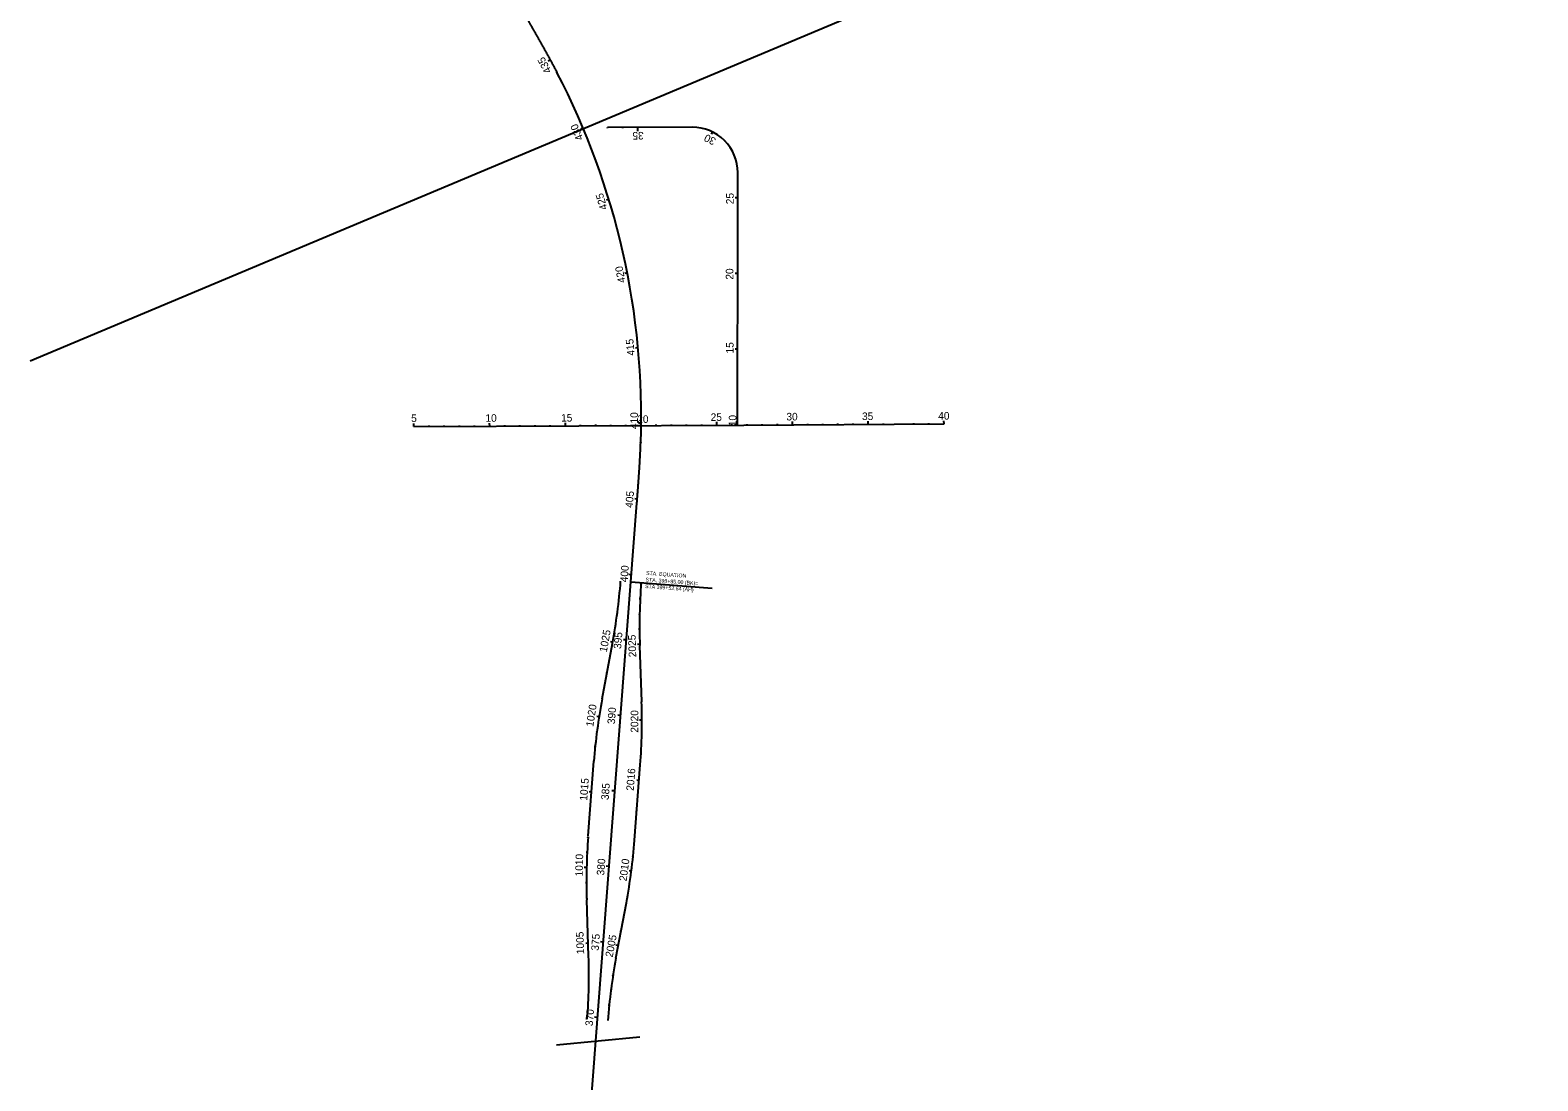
# Model space of a CAD drawing. Extents: x 448091 to 665917, y 1461380 to 1587607.
# Drawn here: x 480103 to 490058, y 1554798 to 1561735 of the extents above; entities that cross this region are included whole.
import ezdxf

# ---------------------------------------------------------------- set-up
doc = ezdxf.new("R2010")
doc.units = 0
for name, color, linetype in [('AsphaltMisc', 7, 'Continuous'), ('Attenuator_ep', 7, 'Continuous'), ('BarrierWall_ep', 7, 'Continuous'), ('TextShtNo', 7, 'Continuous'), ('TextTitle', 7, 'Continuous')]:
    doc.layers.add(name, color=color, linetype=linetype)

msp = doc.modelspace()

# ---------------------------------------------------------------- linework, layer by layer
at = {"layer": 'AsphaltMisc'}
for p, q in [((483913.5, 1561091.9), (483913.5, 1561088.1)), ((484474.5, 1561094.3), (483914.9, 1561091.9)), ((484013.5, 1561092.3), (484013.5, 1561088.6)), ((484113.5, 1561092.7), (484113.6, 1561068.2)), ((484213.5, 1561093.2), (484213.5, 1561089.4)), ((484313.5, 1561093.6), (484313.5, 1561089.9)), ((484413.5, 1561094), (484413.5, 1561090.3)), ((484513.4, 1561092), (484512.9, 1561088.2)), ((484608.7, 1561063.3), (484601, 1561047.6)), ((484689.4, 1561005), (484686.7, 1561002.4)), ((484746.6, 1560923.5), (484743.2, 1560921.9)), ((484774, 1560827.8), (484770.2, 1560827.4)), ((484775.9, 1560459.8), (484775.8, 1560794.3)), ((484775.9, 1560727.9), (484772.1, 1560727.9)), ((484775.9, 1560627.9), (484758.4, 1560627.9)), ((484775.9, 1560527.9), (484772.1, 1560527.9)), ((484775.9, 1560427.9), (484772.1, 1560427.9)), ((484774.9, 1559127.9), (484775.9, 1560459.8)), ((484775.8, 1560327.9), (484772, 1560327.9)), ((484775.7, 1560227.9), (484772, 1560227.9)), ((484775.6, 1560127.9), (484758.1, 1560127.9)), ((484775.6, 1560027.9), (484771.8, 1560027.9)), ((484775.5, 1559927.9), (484771.8, 1559927.9)), ((484775.4, 1559827.9), (484771.7, 1559827.9)), ((484775.4, 1559727.9), (484771.6, 1559727.9)), ((484775.3, 1559627.9), (484757.8, 1559627.9)), ((484775.2, 1559527.9), (484771.5, 1559527.9)), ((484775.1, 1559427.9), (484771.4, 1559427.9)), ((484775.1, 1559327.9), (484771.3, 1559327.9)), ((484775, 1559227.9), (484771.2, 1559227.9)), ((484774.9, 1559127.9), (484753.4, 1559127.9))]:
    msp.add_line(p, q, dxfattribs=at)
msp.add_arc((484475.8, 1560794.3), 300, 0.00667, 90.24889, dxfattribs=at)
at = {"layer": 'Attenuator_ep'}
msp.add_line((484070.1, 1558092.9), (484606.9, 1558052), dxfattribs=at)
msp.add_circle((484070.1, 1558092.9), 1.24, dxfattribs=at)
at = {"layer": 'BarrierWall_ep'}
msp.add_line((480103.3, 1559552.9), (490058.4, 1563731.6), dxfattribs=at)
at = {"layer": 'TextShtNo'}
for p, q in [((482637.5, 1559118.4), (484814.9, 1559128.1)), ((484814.9, 1559128.1), (486137.4, 1559135)), ((484045.9, 1557775.9), (484109.7, 1558612.2)), ((484070.1, 1558092.9), (484109.7, 1558612.2)), ((484070.1, 1558092.9), (484109.7, 1558612.2)), ((483762.6, 1554061.5), (484045.9, 1557775.9)), ((483879.7, 1557320.2), (483948.2, 1557686)), ((484141.1, 1557300.2), (484128.9, 1557672.2)), ((483788.1, 1556415.5), (483825.6, 1556908.1)), ((484094, 1556386.2), (484132.1, 1556884.7)), ((483790.8, 1555622), (483778.6, 1555994)), ((483971.4, 1555608.2), (484039.9, 1555974.1)), ((483579.4, 1555036.9), (484129.2, 1555088.6))]:
    msp.add_line(p, q, dxfattribs=at)
for centre, radius, start, end in [((479226.7, 1559185.3), 4911.1, 357.97112, 27.53647), ((480193.7, 1558388.6), 3819.7, 349.40062, 355.63779), ((487946.6, 1557797.2), 3819.7, 175.63779, 181.87496), ((487634.3, 1556617.6), 3819.7, 169.40062, 175.63779), ((480323.4, 1557175.2), 3819.7, 355.63779, 1.87496), ((487596.2, 1556119), 3819.7, 175.63779, 181.87496), ((480285.4, 1556676.7), 3819.7, 349.40061, 355.63779), ((479973.1, 1555497), 3819.7, 355.63779, 1.87496), ((487726.5, 1554905.5), 3820.2, 169.40061, 175.63779)]:
    msp.add_arc(centre, radius, start, end, dxfattribs=at)
for points in [[(483387, 1561805.2), (483389.7, 1561800.5), (483392.4, 1561795.9), (483395.1, 1561791.2), (483397.8, 1561786.5), (483400.5, 1561781.8), (483403.1, 1561777.1), (483405.8, 1561772.4), (483408.5, 1561767.7), (483411.2, 1561763), (483413.9, 1561758.3), (483416.6, 1561753.7), (483419.3, 1561749), (483422, 1561744.3), (483424.7, 1561739.6), (483427.3, 1561734.9), (483430, 1561730.2), (483432.7, 1561725.5), (483435.4, 1561720.8), (483438.1, 1561716.1), (483440.7, 1561711.4), (483443.4, 1561706.7), (483446.1, 1561702), (483448.8, 1561697.3), (483451.4, 1561692.6), (483454.1, 1561687.9), (483456.8, 1561683.2), (483459.5, 1561678.5), (483462.1, 1561673.8), (483464.8, 1561669.1), (483467.4, 1561664.4), (483470.1, 1561659.7), (483472.8, 1561655), (483475.4, 1561650.3), (483478.1, 1561645.6), (483480.7, 1561640.9), (483483.4, 1561636.2), (483486, 1561631.5), (483488.7, 1561626.7), (483491.3, 1561622), (483493.9, 1561617.3), (483496.6, 1561612.6), (483499.2, 1561607.9), (483501.8, 1561603.1), (483504.5, 1561598.4), (483507.1, 1561593.7), (483509.7, 1561589), (483512.3, 1561584.2), (483514.9, 1561579.5), (483517.5, 1561574.8), (483520.1, 1561570), (483522.7, 1561565.3), (483525.3, 1561560.6), (483527.9, 1561555.8), (483530.5, 1561551.1), (483533.1, 1561546.3), (483535.7, 1561541.6), (483538.3, 1561536.8), (483540.9, 1561532.1), (483543.4, 1561527.3), (483546, 1561522.6), (483548.6, 1561517.8), (483551.1, 1561513), (483553.7, 1561508.3), (483556.2, 1561503.5), (483558.8, 1561498.7), (483561.3, 1561494), (483563.9, 1561489.2), (483566.4, 1561484.4), (483568.9, 1561479.7), (483571.4, 1561474.9), (483573.9, 1561470.1), (483576.5, 1561465.3), (483579, 1561460.5), (483581.5, 1561455.7)], [(484109.7, 1558612.2), (484110.1, 1558617.6), (484110.5, 1558623), (484111, 1558628.4), (484111.4, 1558633.8), (484111.8, 1558639.2), (484112.2, 1558644.6), (484112.6, 1558649.9), (484113, 1558655.3), (484113.4, 1558660.7), (484113.8, 1558666.1), (484114.2, 1558671.5), (484114.6, 1558676.9), (484115, 1558682.3), (484115.4, 1558687.7), (484115.8, 1558693.1), (484116.2, 1558698.5), (484116.7, 1558703.8), (484117, 1558709.2), (484117.4, 1558714.6), (484117.8, 1558720), (484118.2, 1558725.4), (484118.6, 1558730.8), (484119, 1558736.2), (484119.4, 1558741.6), (484119.8, 1558747), (484120.2, 1558752.4), (484120.6, 1558757.8), (484120.9, 1558763.1), (484121.3, 1558768.5), (484121.7, 1558773.9), (484122.1, 1558779.3), (484122.4, 1558784.7), (484122.8, 1558790.1), (484123.2, 1558795.5), (484123.5, 1558800.9), (484123.9, 1558806.3), (484124.3, 1558811.7), (484124.6, 1558817.1), (484125, 1558822.5), (484125.3, 1558827.9), (484125.7, 1558833.3), (484126, 1558838.7), (484126.3, 1558844), (484126.7, 1558849.4), (484127, 1558854.8), (484127.3, 1558860.2), (484127.7, 1558865.6), (484128, 1558871), (484128.3, 1558876.4), (484128.6, 1558881.8), (484128.9, 1558887.2), (484129.2, 1558892.6), (484129.5, 1558898), (484129.8, 1558903.4), (484130.1, 1558908.8), (484130.4, 1558914.2), (484130.7, 1558919.6), (484131, 1558925), (484131.2, 1558930.4), (484131.5, 1558935.8), (484131.8, 1558941.2), (484132, 1558946.6), (484132.3, 1558952), (484132.5, 1558957.4), (484132.8, 1558962.8), (484133, 1558968.2), (484133.3, 1558973.6), (484133.5, 1558979), (484133.7, 1558984.4), (484133.9, 1558989.8), (484134.1, 1558995.2), (484134.3, 1559000.6), (484134.5, 1559006), (484134.7, 1559011.4)]]:
    msp.add_spline(points, degree=3, dxfattribs=at)
at = {"layer": 'TextTitle'}
for p, q in [((483440.5, 1561711.9), (483436.8, 1561709.7)), ((483440.5, 1561711.9), (483437.5, 1561710.2)), ((483489.7, 1561624.8), (483486, 1561622.7)), ((483489.7, 1561624.8), (483486.8, 1561623.2)), ((483538, 1561537.3), (483523.6, 1561529.4)), ((483538.1, 1561537.3), (483534.3, 1561535.2)), ((483585, 1561449), (483581.2, 1561447)), ((483585, 1561449), (483582, 1561447.4)), ((483715.1, 1561178.7), (483711.1, 1561176.9)), ((483715, 1561178.7), (483711.9, 1561177.3)), ((483754.7, 1561086.9), (483739.6, 1561080.5)), ((483754.7, 1561086.9), (483750.7, 1561085.2)), ((483792.5, 1560994.3), (483788.5, 1560992.7)), ((483792.5, 1560994.3), (483789.3, 1560993)), ((483828.4, 1560901), (483824.3, 1560899.4)), ((483828.4, 1560901), (483825.2, 1560899.8)), ((483862.4, 1560806.9), (483858.3, 1560805.5)), ((483862.4, 1560806.9), (483859.1, 1560805.8)), ((483894.4, 1560712.2), (483890.3, 1560710.8)), ((483894.4, 1560712.2), (483891.2, 1560711.1)), ((483924.5, 1560616.8), (483908.8, 1560612.1)), ((483924.5, 1560616.8), (483920.4, 1560615.6)), ((483952.7, 1560520.9), (483948.6, 1560519.7)), ((483952.7, 1560520.9), (483949.4, 1560520)), ((483978.9, 1560424.4), (483974.8, 1560423.3)), ((483978.9, 1560424.4), (483975.6, 1560423.5)), ((484003.2, 1560327.4), (483999, 1560326.4)), ((484003.2, 1560327.4), (483999.9, 1560326.6)), ((484025.4, 1560229.9), (484021.2, 1560229)), ((484025.4, 1560229.9), (484022.1, 1560229.2)), ((484045.7, 1560132), (484029.6, 1560128.8)), ((484045.7, 1560132), (484041.5, 1560131.1)), ((484064, 1560033.6), (484059.7, 1560032.9)), ((484064, 1560033.6), (484060.6, 1560033.1)), ((484080.2, 1559935), (484076, 1559934.3)), ((484080.2, 1559935), (484076.9, 1559934.5)), ((484094.5, 1559836), (484090.2, 1559835.4)), ((484094.5, 1559836), (484091.1, 1559835.6)), ((484106.7, 1559736.8), (484102.5, 1559736.3)), ((484106.7, 1559736.8), (484103.4, 1559736.4)), ((484117, 1559637.3), (484100.6, 1559635.8)), ((484117, 1559637.3), (484112.7, 1559636.9)), ((484125.2, 1559537.6), (484120.9, 1559537.3)), ((484125.2, 1559537.6), (484121.8, 1559537.4)), ((484131.3, 1559437.8), (484127, 1559437.6)), ((484131.3, 1559437.8), (484127.9, 1559437.6)), ((484135.4, 1559337.9), (484131.1, 1559337.8)), ((484135.4, 1559337.9), (484132, 1559337.8)), ((484137.5, 1559237.9), (484133.2, 1559237.9)), ((484137.5, 1559237.9), (484134.1, 1559237.9)), ((482637.5, 1559118.4), (482637.4, 1559139.1)), ((482737.5, 1559118.8), (482737.4, 1559124.6)), ((482837.5, 1559119.3), (482837.4, 1559125)), ((482937.5, 1559119.7), (482937.4, 1559125.5)), ((483037.5, 1559120.1), (483037.4, 1559125.9)), ((483137.5, 1559120.6), (483137.4, 1559141.3)), ((483237.5, 1559121), (483237.4, 1559126.8)), ((483337.5, 1559121.5), (483337.4, 1559127.2)), ((483437.4, 1559121.9), (483437.4, 1559127.7)), ((483537.4, 1559122.4), (483537.4, 1559128.1)), ((483637.4, 1559122.8), (483637.4, 1559143.6)), ((483737.4, 1559123.3), (483737.4, 1559129)), ((483837.4, 1559123.7), (483837.4, 1559131.5)), ((483837.4, 1559123.7), (483837.4, 1559129.5)), ((483937.4, 1559124.2), (483937.4, 1559129.9)), ((484037.4, 1559124.6), (484037.4, 1559130.4)), ((484137.6, 1559137.9), (484121.2, 1559138.1)), ((484137.6, 1559137.9), (484133.3, 1559138)), ((484137.4, 1559125.1), (484137.4, 1559135.8)), ((484237.4, 1559125.5), (484237.4, 1559131.3)), ((484337.4, 1559126), (484337.4, 1559131.7)), ((484437.4, 1559126.4), (484437.4, 1559132.2)), ((484537.4, 1559126.9), (484537.4, 1559132.6)), ((484637.4, 1559127.3), (484637.3, 1559148.1)), ((484737.4, 1559127.7), (484737.4, 1559133.5)), ((484837.4, 1559128.2), (484837.4, 1559134)), ((484937.4, 1559128.7), (484937.4, 1559134.5)), ((485037.4, 1559129.2), (485037.4, 1559135)), ((485137.4, 1559129.8), (485137.3, 1559150.5)), ((485237.4, 1559130.3), (485237.4, 1559136)), ((485337.4, 1559130.8), (485337.4, 1559136.6)), ((485437.4, 1559131.3), (485437.4, 1559137.1)), ((485537.4, 1559131.8), (485537.4, 1559137.6)), ((485637.4, 1559132.4), (485637.3, 1559153.1)), ((485737.4, 1559132.9), (485737.4, 1559138.6)), ((485837.4, 1559133.4), (485837.4, 1559139.2)), ((485937.4, 1559133.9), (485937.4, 1559139.7)), ((486037.4, 1559134.4), (486037.4, 1559140.2)), ((486137.4, 1559135), (486137.3, 1559155.7)), ((484135.6, 1559037.9), (484131.3, 1559038.1)), ((484135.6, 1559037.9), (484132.2, 1559038)), ((484131.6, 1558938), (484127.3, 1558938.2)), ((484131.6, 1558938), (484128.2, 1558938.2)), ((484126, 1558838.2), (484121.7, 1558838.5)), ((484126, 1558838.2), (484122.6, 1558838.4)), ((484119.2, 1558738.4), (484114.9, 1558738.7)), ((484119.2, 1558738.4), (484115.8, 1558738.7)), ((484111.7, 1558638.7), (484095.4, 1558639.9)), ((484111.7, 1558638.7), (484107.5, 1558639)), ((484104.1, 1558539), (484099.9, 1558539.3)), ((484104.1, 1558539), (484100.7, 1558539.2)), ((484096.5, 1558439.3), (484092.2, 1558439.6)), ((484096.5, 1558439.3), (484093.1, 1558439.5)), ((484088.9, 1558339.6), (484084.6, 1558339.9)), ((484088.9, 1558339.6), (484085.5, 1558339.8)), ((484081.3, 1558239.9), (484077, 1558240.2)), ((484081.3, 1558239.9), (484077.9, 1558240.1)), ((484001.7, 1558090.4), (483996, 1558090.9)), ((484073.7, 1558140.1), (484057.4, 1558141.4)), ((484073.7, 1558140.1), (484069.4, 1558140.5)), ((484137.3, 1558080.1), (484131.6, 1558080.5)), ((483992.6, 1557990.9), (483986.9, 1557991.4)), ((484063.6, 1558008.2), (484058.7, 1558008.6)), ((484131.2, 1557980.3), (484125.5, 1557980.5)), ((483980.9, 1557891.5), (483975.2, 1557892.3)), ((484056, 1557908.5), (484051.1, 1557908.8)), ((484127.8, 1557880.3), (484122, 1557880.5)), ((483966.6, 1557792.6), (483960.9, 1557793.5)), ((484048.4, 1557808.8), (484043.5, 1557809.1)), ((484126.9, 1557780.3), (484121.2, 1557780.3)), ((483949.7, 1557694), (483934.2, 1557696.9)), ((484040.8, 1557709), (484020.9, 1557710.6)), ((484128.6, 1557680.4), (484112.9, 1557679.9)), ((483931.3, 1557595.7), (483925.7, 1557596.8)), ((484033.2, 1557609.3), (484028.2, 1557609.7)), ((484131.9, 1557580.4), (484126.2, 1557580.2)), ((483912.9, 1557497.4), (483907.3, 1557498.5)), ((484025.6, 1557509.6), (484020.6, 1557510)), ((484135.2, 1557480.5), (484129.4, 1557480.3)), ((483894.5, 1557399.1), (483888.9, 1557400.2)), ((484018, 1557409.9), (484013, 1557410.3)), ((484138.4, 1557380.5), (484132.7, 1557380.3)), ((483859.6, 1557202.2), (483844, 1557204.6)), ((484002.8, 1557210.5), (483982.9, 1557212)), ((484143.1, 1557180.6), (484127.4, 1557180.6)), ((483845.6, 1557103.2), (483839.9, 1557103.9)), ((483995.2, 1557110.8), (483990.2, 1557111.2)), ((484141.9, 1557080.6), (484136.2, 1557080.7)), ((483834.1, 1557003.9), (483828.4, 1557004.4)), ((483987.6, 1557011.1), (483982.6, 1557011.5)), ((484138.2, 1556980.7), (484132.4, 1556981)), ((483825.3, 1556904.3), (483819.6, 1556904.7)), ((483980, 1556911.4), (483975, 1556911.7)), ((484131.8, 1556880.9), (484126, 1556881.3)), ((483817.7, 1556804.5), (483812, 1556805)), ((483972.4, 1556811.7), (483967.4, 1556812)), ((484124.2, 1556781.2), (484108.5, 1556782.4)), ((483810.1, 1556704.8), (483794.4, 1556706)), ((483964.8, 1556711.9), (483944.8, 1556713.5)), ((484116.5, 1556681.5), (484110.8, 1556681.9)), ((483802.5, 1556605.1), (483796.8, 1556605.6)), ((483957.2, 1556612.2), (483952.2, 1556612.6)), ((484108.9, 1556581.8), (484103.2, 1556582.2)), ((483794.9, 1556505.4), (483789.2, 1556505.9)), ((483949.6, 1556512.5), (483944.6, 1556512.9)), ((484101.3, 1556482), (484095.6, 1556482.5)), ((483787.3, 1556405.7), (483781.6, 1556406.1)), ((483942, 1556412.8), (483937, 1556413.2)), ((484093.7, 1556382.3), (484088, 1556382.8)), ((483781.1, 1556305.9), (483775.4, 1556306.2)), ((483934.3, 1556313.1), (483929.4, 1556313.5)), ((484084.7, 1556282.7), (484079, 1556283.3)), ((483777.5, 1556206), (483761.8, 1556206.3)), ((483926.7, 1556213.4), (483906.8, 1556214.9)), ((484073.1, 1556183.4), (484057.5, 1556185.4)), ((483776.6, 1556106), (483770.8, 1556106)), ((483919.1, 1556113.7), (483914.1, 1556114.1)), ((484058.9, 1556084.4), (484053.2, 1556085.3)), ((483778.2, 1556006), (483772.5, 1556005.8)), ((483911.5, 1556014), (483906.5, 1556014.3)), ((484042.1, 1555985.9), (484036.5, 1555986.9)), ((483781.5, 1555906), (483775.7, 1555905.9)), ((483903.9, 1555914.3), (483898.9, 1555914.6)), ((484023.7, 1555887.6), (484018.1, 1555888.6)), ((483784.7, 1555806.1), (483779, 1555805.9)), ((483896.3, 1555814.5), (483891.3, 1555814.9)), ((484005.3, 1555789.3), (483999.7, 1555790.3)), ((483788, 1555706.2), (483772.3, 1555705.6)), ((483888.7, 1555714.8), (483868.8, 1555716.4)), ((483986.9, 1555691), (483971.5, 1555693.9)), ((483791.2, 1555606.2), (483785.5, 1555606)), ((483881.1, 1555615.1), (483876.1, 1555615.5)), ((483968.6, 1555592.7), (483962.9, 1555593.7)), ((483792.8, 1555506.2), (483787.1, 1555506.2)), ((483873.5, 1555515.4), (483868.5, 1555515.8)), ((483951.9, 1555494.1), (483946.2, 1555495)), ((483791.7, 1555406.2), (483786, 1555406.4)), ((483865.9, 1555415.7), (483860.9, 1555416.1)), ((483937.8, 1555395.1), (483932.1, 1555395.8)), ((483788, 1555306.3), (483782.3, 1555306.6)), ((483858.3, 1555316), (483853.3, 1555316.4)), ((483926.2, 1555295.8), (483920.5, 1555296.3)), ((483850.7, 1555216.3), (483830.7, 1555217.8)), ((483843.1, 1555116.6), (483838.1, 1555117)), ((483835.5, 1555016.9), (483830.5, 1555017.2)), ((483835.5, 1555016.9), (483832.1, 1555017.1)), ((483827.9, 1554917.2), (483822.9, 1554917.5)), ((483827.9, 1554917.2), (483824.5, 1554917.4)), ((483820.3, 1554817.4), (483815.3, 1554817.8)), ((483820.3, 1554817.4), (483816.9, 1554817.7))]:
    msp.add_line(p, q, dxfattribs=at)
for centre in [(483581.5, 1561455.7), (484134.7, 1559011.4)]:
    msp.add_circle(centre, 1, dxfattribs=at)

# ---------------------------------------------------------------- texts
at = {"layer": 'AsphaltMisc'}
for s, rotation, p in [('35', 180.24889, (484154.3, 1561063.2)), ('30', 153.71318, (484636.2, 1561018.1)), ('25', 90.00667, (484748.7, 1560585.7)), ('20', 89.95889, (484746.4, 1560087.8)), ('15', 89.95889, (484748.1, 1559600.3)), ('10', 89.95889, (484766.3, 1559120.2))]:
    msp.add_text(s, height=50, rotation=rotation, dxfattribs=at).set_placement(p)
at = {"layer": 'Attenuator_ep'}
for s, p in [('STA 399+52.64 (AH)', (484162.7, 1558052)), ('STA. 398+85.00 (BK)=', (484166, 1558095.6)), ('STA. EQUATION', (484169.2, 1558139.3))]:
    msp.add_text(s, height=25, rotation=355.73739, dxfattribs=at).set_placement(p)
at = {"layer": 'TextTitle'}
for s, rotation, p in [('435', 118.48981, (483547.7, 1561465.4)), ('430', 112.78094, (483757.3, 1561018.4)), ('425', 106.94761, (483916.3, 1560556.5)), ('420', 101.11427, (484035, 1560071.4)), ('415', 95.28094, (484095.6, 1559588.2)), ('5', 0.25611, (482619.1, 1559148)), ('10', 0.25611, (483109.6, 1559149.2)), ('15', 0.25611, (483609, 1559150.5)), ('410', 89.44761, (484115.7, 1559100.7)), ('20', 0.25611, (484111.9, 1559141.9)), ('25', 0.25611, (484596.6, 1559154.9)), ('30', 0.2975, (485096.8, 1559158.2)), ('35', 0.2975, (485596.2, 1559160.9)), ('40', 0.2975, (486099.3, 1559163.5)), ('405', 85.64807, (484082.2, 1558579.7)), ('400', 85.63779, (484048, 1558088.5)), ('1025', 79.52244, (483910.4, 1557625.3)), ('395', 85.63781, (484005.4, 1557648.1)), ('2025', 91.75313, (484105.4, 1557595.8)), ('1020', 81.19546, (483821.4, 1557133.4)), ('390', 85.63781, (483964, 1557151.6)), ('2020', 90.08011, (484118.8, 1557096.9)), ('1015', 85.63779, (483781.2, 1556646.4)), ('2016', 85.63779, (484088.5, 1556711.7)), ('385', 85.63781, (483922.7, 1556650.8)), ('1010', 88.69546, (483751.8, 1556147.4)), ('380', 85.63781, (483893.4, 1556153.2)), ('2010', 82.58011, (484041.5, 1556114.1)), ('1005', 91.87496, (483761.7, 1555635.4)), ('375', 85.63781, (483857, 1555656)), ('2005', 79.40061, (483949.4, 1555611.5)), ('370', 85.63781, (483818.1, 1555158.6))]:
    msp.add_text(s, height=50, rotation=rotation, dxfattribs=at).set_placement(p)

doc.saveas('drawing.dxf')
